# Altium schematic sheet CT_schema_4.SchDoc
size 186 x 134 mm
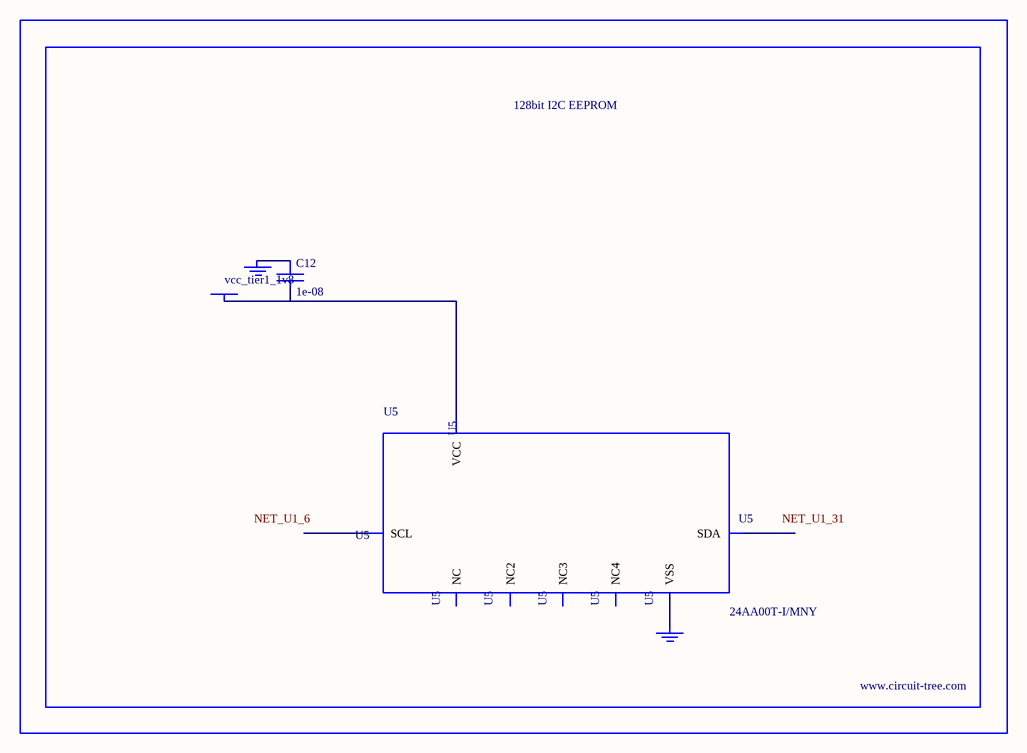
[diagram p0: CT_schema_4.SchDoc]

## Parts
BORDER3  (no value)
C12  1e-08  [C0402]
GND_INSTANCE_3_0  (no value)
GND_INSTANCE_3_1  (no value)
POWER_INSTANCE_3_0  vcc_tier1_1v8
U5  24AA00T-I/MNY  [TDFN-8/6MM]

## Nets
NetC12_1: C12.1 GND_INSTANCE_3_0.0(GND)
NetC12_2: C12.2 POWER_INSTANCE_3_0.0(PWR) U5.8(VCC)
NetGND_INSTANCE_3_1_0: GND_INSTANCE_3_1.0(GND) U5.4(VSS)

Not connected (* = marked no-connect by the designer): U5 1(NC) 2(NC2) 3(NC3) 5(SDA) 6(SCL) 7(NC4)

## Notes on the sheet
- Labels drawn without touching a wire or pin: NET_U1_6, NET_U1_31

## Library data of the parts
BORDER3 = BORDER_PAGE3
C12 = C0402C103K3RAC
GND_INSTANCE_3_0 GND_INSTANCE_3_1 = GND
POWER_INSTANCE_3_0 = PWR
